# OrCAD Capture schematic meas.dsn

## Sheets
1 UI: size A
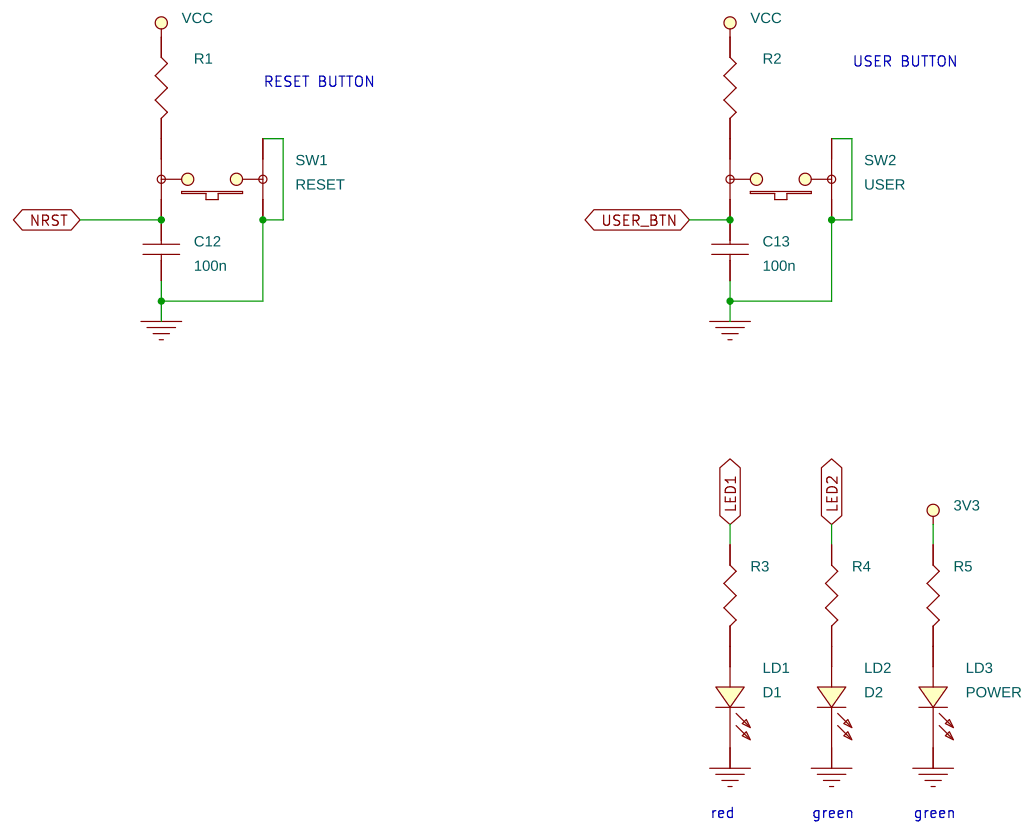
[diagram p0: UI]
2 POWER: size A
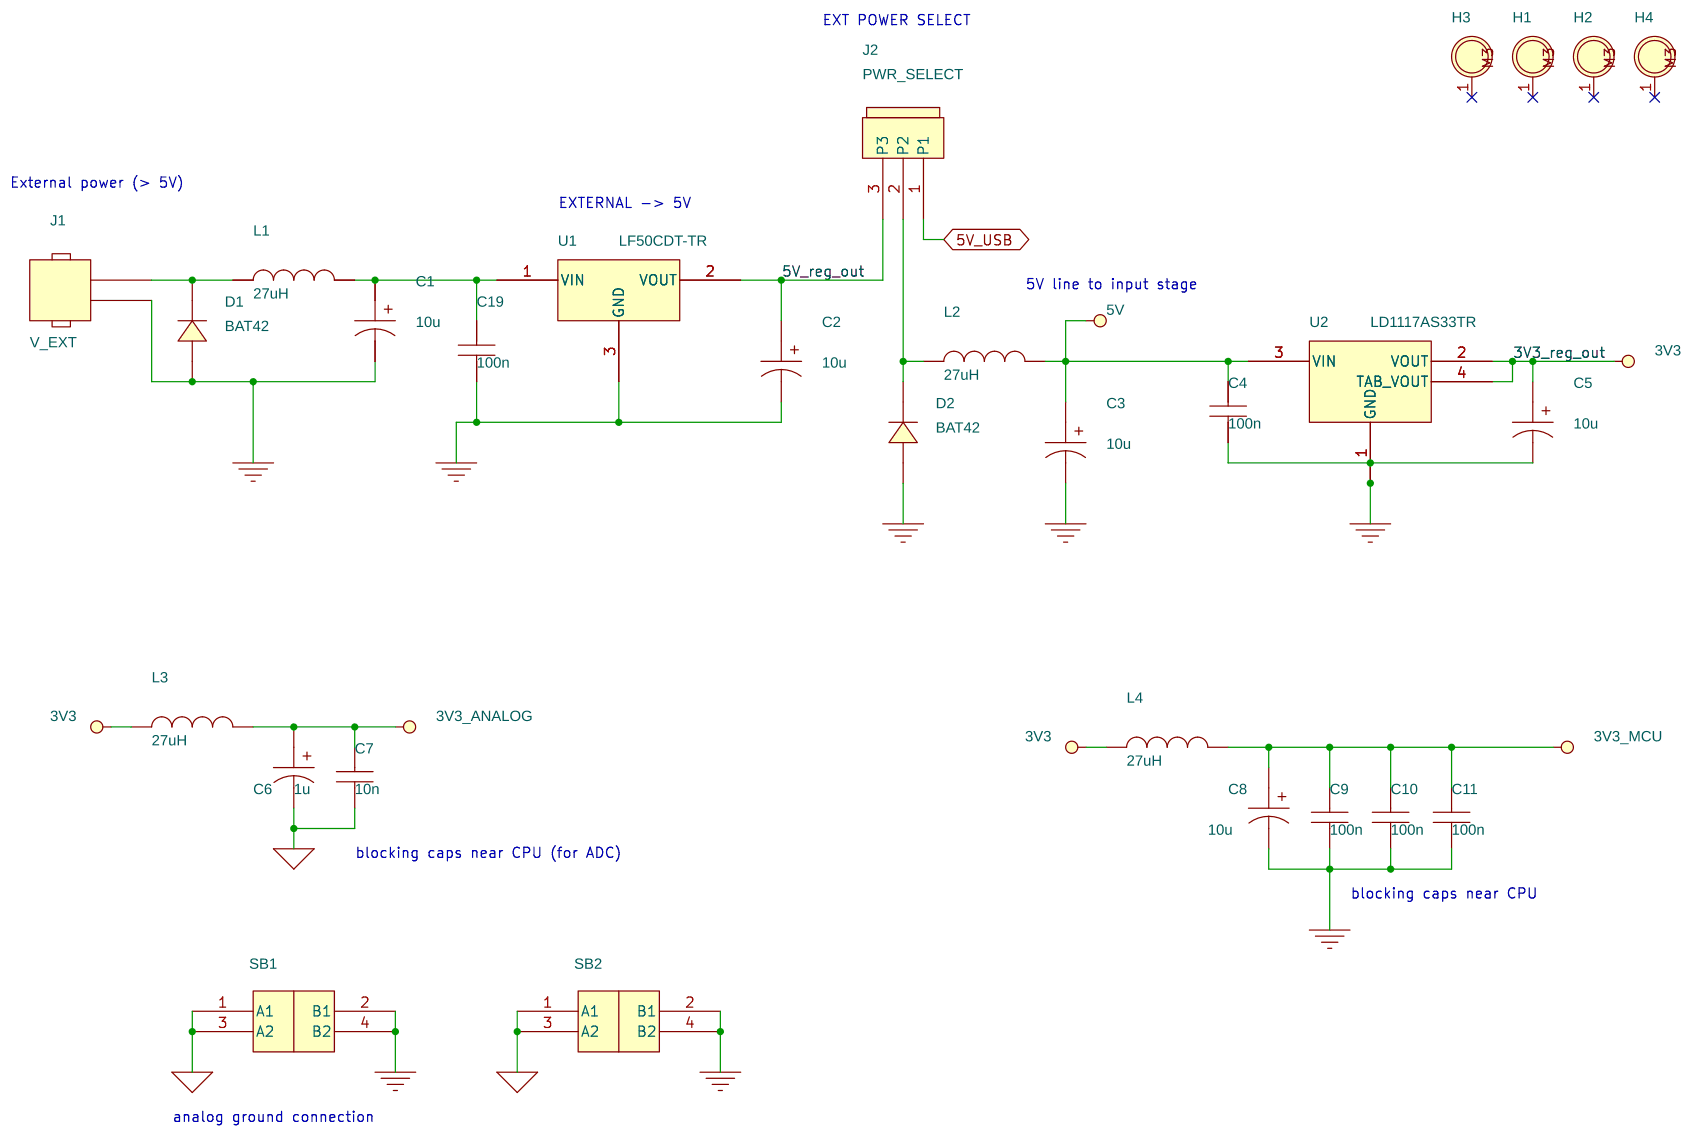
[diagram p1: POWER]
3 INPUT: size A; title: Current measurement and processing; rev: 1
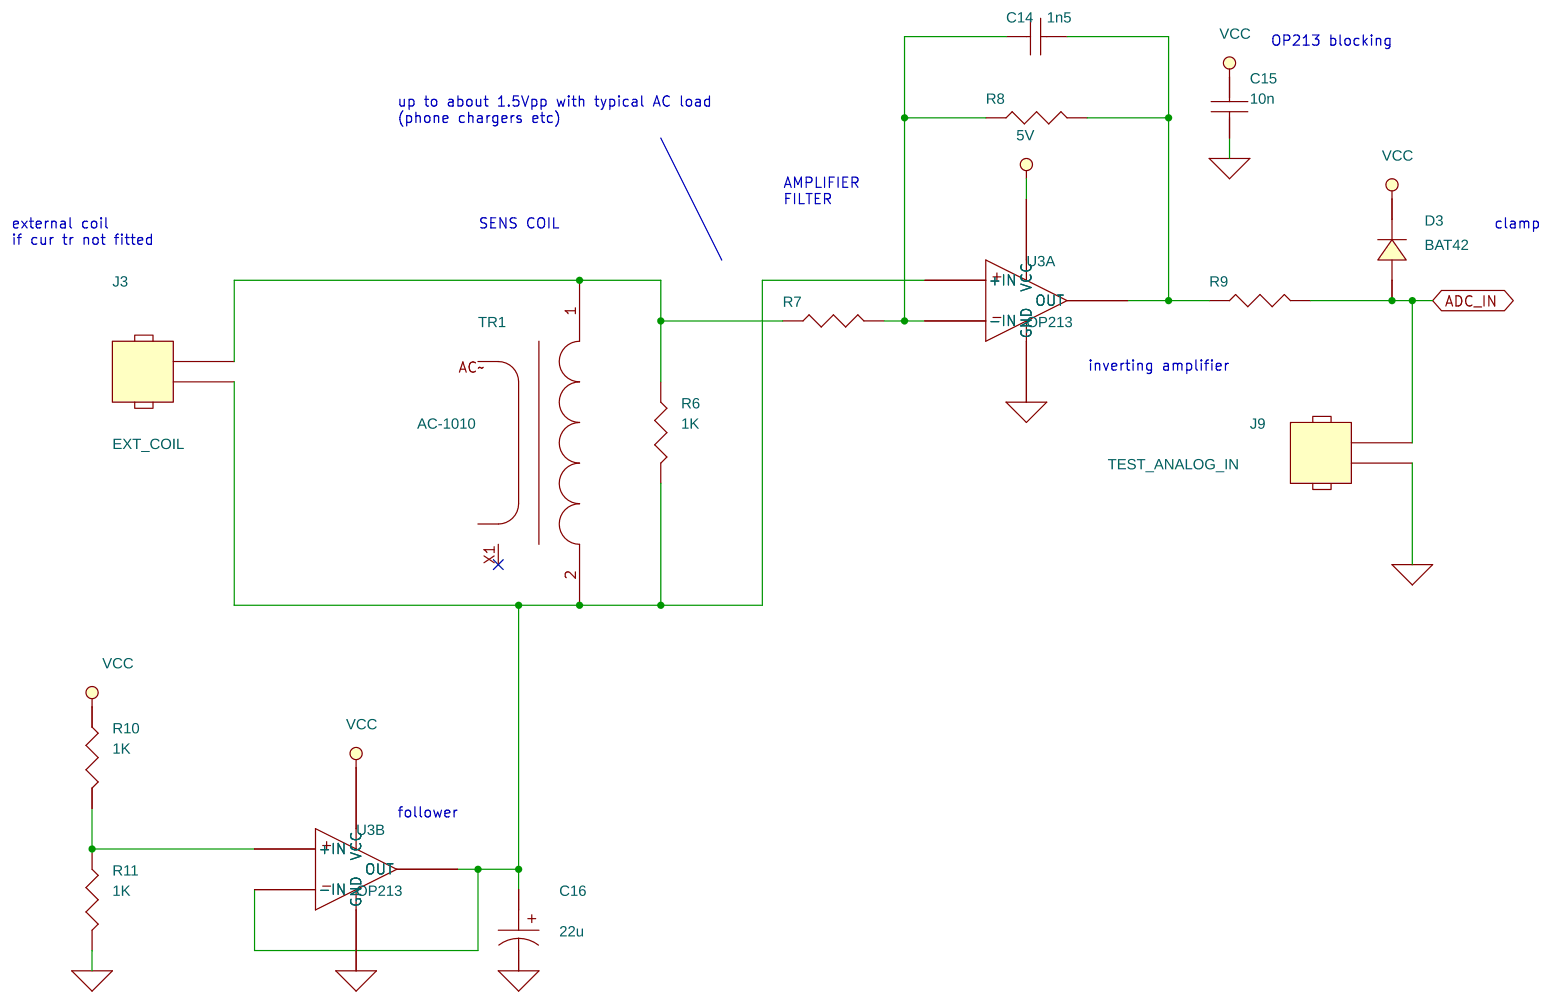
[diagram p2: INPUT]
4 MPU: size B; title: AC current analysys
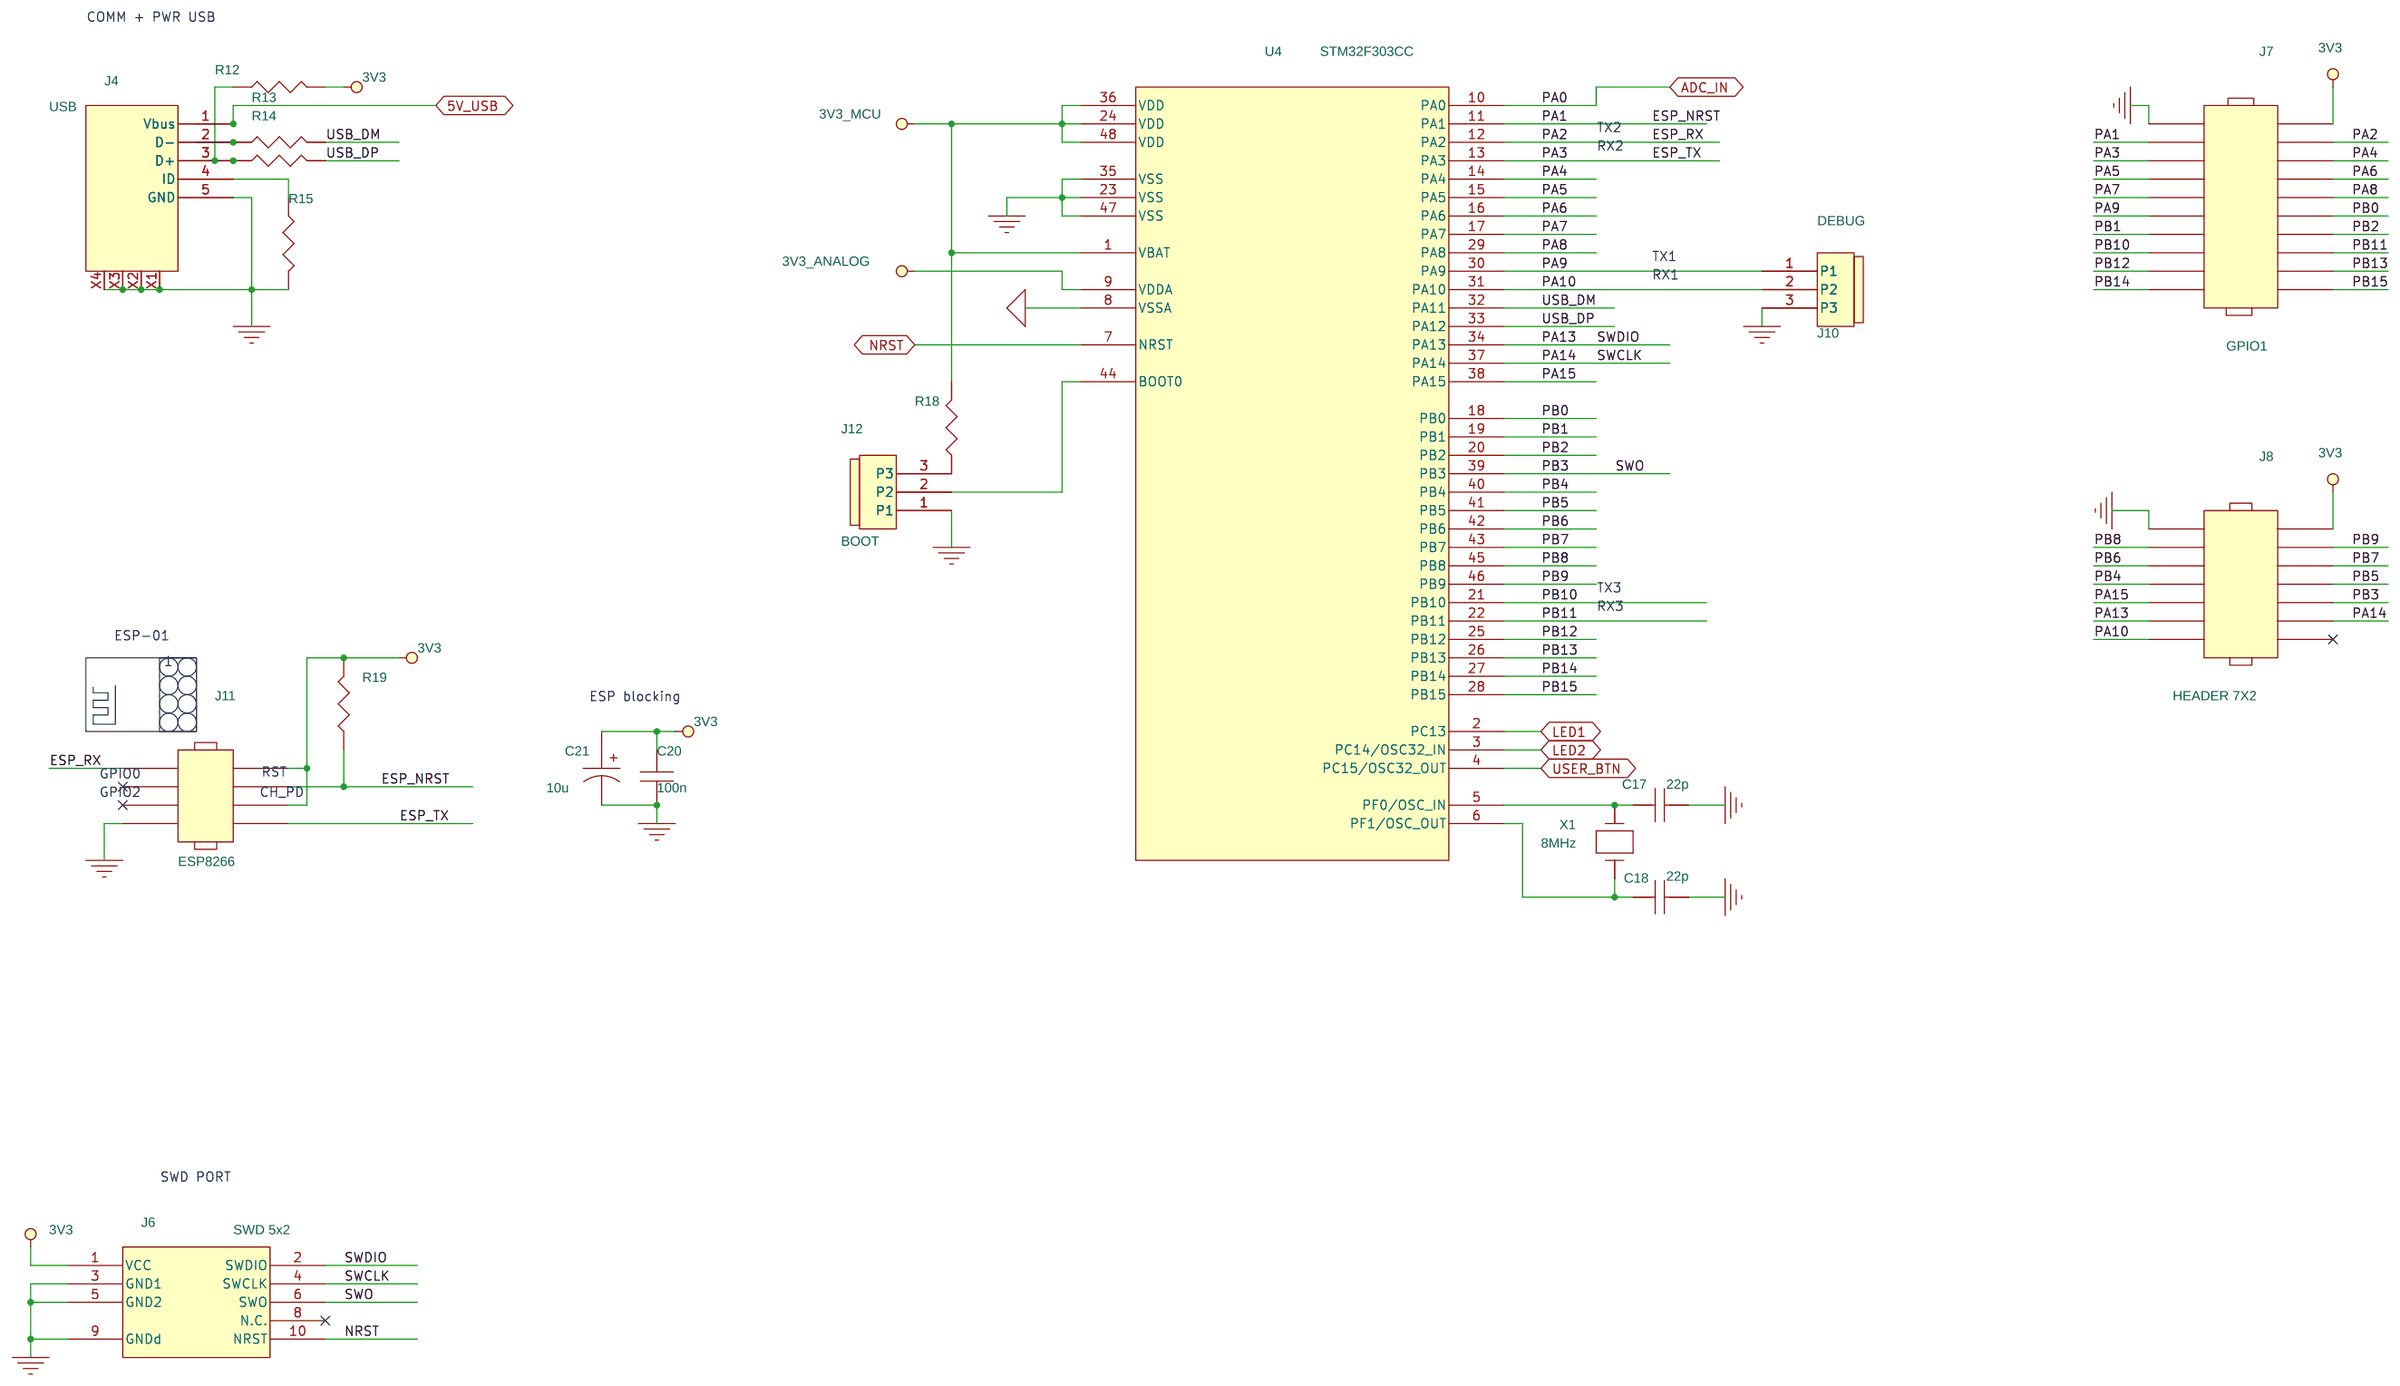
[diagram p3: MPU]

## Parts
sheet INPUT
C14  1n5  [s_0805]
C15  10n  [s_0805]
C16  22u  [s_1206_cap]
D3  BAT42  [s_minimelf]
J3  EXT_COIL  [t_sip2]
J9  TEST_ANALOG_IN  [t_sip2]
R6  1K  [s_0805]
R7  10k  [s_0805]
R8  20k  [s_0805]
R9  470R  [s_0805]
R10  1K  [s_0805]
R11  1K  [s_0805]
TR1  AC-1010  [t_talema_cur_tr]
U3  OP213  [t_dip8]  (sections A,B)
sheet MPU
C17  22p  [s_0805]
C18  22p  [s_0805]
C20  100n  [s_0805]
C21  10u  [s_1206_cap]
J4  USB  [s_usb_mini_b]
J6  SWD 5x2  [t_header_swd]
J7  GPIO1  [t_header10x2]
J8  HEADER 7X2  [t_header7x2]
J10  DEBUG  [t_sip3]
J11  ESP8266  [t_header4x2]
J12  BOOT  [t_sip3]
R12  1k  [s_0805]
R13  22  [s_0805]
R14  22  [s_0805]
R15  100k  [s_0805]
R18  10k  [s_0805]
R19  10k  [s_0805]
U4  STM32F303CC  [s_lqfp48]
X1  8MHz  [t_xtal50]
sheet POWER
C1  10u  [s_1206_cap]
C2  10u  [s_1206_cap]
C3  10u  [s_1206_cap]
C4  100n  [s_0805]
C5  10u  [s_1206_cap]
C6  1u  [s_1206_cap]
C7  10n  [s_0805]
C8  10u  [s_1206_cap]
C9  100n  [s_0805]
C10  100n  [s_0805]
C11  100n  [s_0805]
C19  100n  [s_0805]
D1  BAT42  [s_minimelf]
D2  BAT42  [s_minimelf]
H1  MOUNT HOLE M3  [mount_hole_m3]
H2  MOUNT HOLE M3  [mount_hole_m3]
H3  MOUNT HOLE M3  [mount_hole_m3]
H4  MOUNT HOLE M3  [mount_hole_m3]
J1  V_EXT  [t_power_con]
J2  PWR_SELECT  [t_sip3]
L1  27uH  [s_1210]
L2  27uH  [s_1210]
L3  27uH  [s_1210]
L4  27uH  [s_1210]
SB1  AGND BRIDGE  [t_agnd_bridge]
SB2  AGND BRIDGE  [t_agnd_bridge]
U1  LF50CDT-TR  [s_dpak]
U2  LD1117AS33TR  [s_sot223]
sheet UI
C12  100n  [s_0805]
C13  100n  [s_0805]
LD1  D1  [s_0805_led]
LD2  D2  [s_0805_led]
LD3  POWER  [s_0805_led]
R1  100k  [s_0805]
R2  100k  [s_0805]
R3  150  [s_0805]
R4  150  [s_0805]
R5  150  [s_0805]
SW1  RESET  [t_button_ksm]
SW2  USER  [t_button_ksm]

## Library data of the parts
C4 C7 C9-C15 C17-C20 = CAPACITOR_NON-POL
C1-C3 C5 C6 C8 C16 C21 = CAP_POL
D1-D3 = DIODE
J1 J3 J9 = HEADER_2
R1-R15 R18 R19 = RESISTOR
TR1 = ac-1010
U3 = OP213
J4 = USB_MINI
J6 = SWD_5x2
J7 = HEADER_10X2
J8 = HEADER_7X2
J2 J10 J12 = JUMPER_3
J11 = HEADER_4X2
U4 = stm32f303cct6
X1 = CRYSTAL
H1-H4 = MOUNT_HOLE_M3
L1-L4 = INDUCTOR
SB1 SB2 = AGND_BRIDGE
U1 = LF50CDT-TR
U2 = LD1117AS33TR
LD1-LD3 = LED
SW1 SW2 = SW_PUSHBUTTON-SPST-2

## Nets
3V3: C5.1 C20.1 C21.1 J6.1(VCC) J7.2 J8.2 J11.2 J11.6 L3.1 L4.1 R1.1 R2.1 R5.1 R12.2 R19.2 U2.2(VOUT) U2.4(TAB_VOUT)
3V3_ANALOG: C6.1 C7.1 D3.1(K) L3.2 R10.1 U4.9(VDDA)
3V3_MCU: C8.1 C9.1 C10.1 C11.1 L4.2 R18.2 U4.1(VBAT) U4.24(VDD) U4.36(VDD) U4.48(VDD)
5V: C3.1 C4.1 C15.1 L2.2 U2.3(VIN) U3.8(VCC)
5V_reg_out: C2.1 J2.3(P3) U1.2(VOUT)
5V_USB: J2.1(P1) J4.1(Vbus)
GND: C1.2 C2.2 C3.2 C4.2 C5.2 C8.2 C9.2 C10.2 C11.2 C12.2 C13.2 C17.2 C18.2 C19.2 C20.2 C21.2 D1.2(A) D2.2(A) J1.2 J4.5(GND) J4.X1 J4.X2 J4.X3 J4.X4 J6.3(GND1) J6.5(GND2) J6.9(GNDd) J7.1 J8.1 J10.3(P3) J11.7 J12.1(P1) LD1.1(CATHODE) LD2.1(CATHODE) LD3.1(CATHODE) R15.2 SB1.2(B1) SB1.4(B2) SB2.2(B1) SB2.4(B2) SW1.1 SW1.2 SW2.1 SW2.2 U1.3(GND) U2.1(GND) U4.23(VSS) U4.35(VSS) U4.47(VSS)
GNDA: C6.2 C7.2 C15.2 C16.2 J9.2 R11.2 SB1.1(A1) SB1.3(A2) SB2.1(A1) SB2.3(A2) U3.4(GND) U4.8(VSSA)
ADC_IN: D3.2(A) J9.1 R9.2 U4.10(PA0)
ESP_NRST: J7.3 J11.4 R19.1 U4.11(PA1)
ESP_RX: J7.4 J11.1 U4.12(PA2)
ESP_TX: J7.5 J11.8 U4.13(PA3)
LED1: R3.1 U4.2(PC13)
LED2: R4.1 U4.3(PC14/OSC32_IN)
NRST: C12.1 J6.10(NRST) SW1.4 U4.7(NRST)
PA4: J7.6 U4.14(PA4)
PA5: J7.7 U4.15(PA5)
PA6: J7.8 U4.16(PA6)
PA7: J7.9 U4.17(PA7)
PA8: J7.10 U4.29(PA8)
PA9: J7.11 J10.1(P1) U4.30(PA9)
PA10: J8.13 J10.2(P2) U4.31(PA10)
PA13: J6.2(SWDIO) J8.11 U4.34(PA13)
PA14: J6.4(SWCLK) J8.12 U4.37(PA14)
PA15: J8.9 U4.38(PA15)
PB0: J7.12 U4.18(PB0)
PB1: J7.13 U4.19(PB1)
PB2: J7.14 U4.20(PB2)
PB3: J6.6(SWO) J8.10 U4.39(PB3)
PB4: J8.7 U4.40(PB4)
PB5: J8.8 U4.41(PB5)
PB6: J8.5 U4.42(PB6)
PB7: J8.6 U4.43(PB7)
PB8: J8.3 U4.45(PB8)
PB9: J8.4 U4.46(PB9)
PB10: J7.15 U4.21(PB10)
PB11: J7.16 U4.22(PB11)
PB12: J7.17 U4.25(PB12)
PB13: J7.18 U4.26(PB13)
PB14: J7.19 U4.27(PB14)
PB15: J7.20 U4.28(PB15)
USB_DM: R13.2 U4.32(PA11)
USB_DP: R14.2 U4.33(PA12)
USER_BTN: C13.1 SW2.4 U4.4(PC15/OSC32_OUT)
N31498: J4.3(D+) R12.1 R14.1
N31517: J4.2(D-) R13.1
N33713: C17.1 U4.5(PF0/OSC_IN) X1.1
N33722: C18.1 U4.6(PF1/OSC_OUT) X1.2
N47255: J3.1 R6.1 R7.1 TR1.1
N47331: C14.1 R7.2 R8.1 U3.2(-IN)
N47339: C14.2 R8.2 R9.1 U3.1(OUT)
N47545: C16.1 J3.2 R6.2 TR1.2 U3.3(+IN) U3.6(-IN) U3.7(OUT)
N50175: C1.1 C19.1 L1.2 U1.1(VIN)
N50285: D2.1(K) J2.2(P2) L2.1
N51670: D1.1(K) J1.1 L1.1
N101209: R10.2 R11.1 U3.5(+IN)
N111212: J4.4(ID) R15.1
N117874: R1.2 SW1.3
N117879: R2.2 SW2.3
N127573: J12.2(P2) U4.44(BOOT0)
N127616: J12.3(P3) R18.1
N127774: LD1.2(ANODE) R3.2
N127776: LD2.2(ANODE) R4.2
N127798: LD3.2(ANODE) R5.2

Not connected (* = marked no-connect by the designer): H1 1*; H2 1*; H3 1*; H4 1*; J6 8(N.C.)*; J8 14*; J11 3* 5*; TR1 X1*

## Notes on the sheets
sheet 1
- USER BUTTON
- RESET BUTTON
- red
- green
- green
sheet 2
- EXT POWER SELECT
- External power (> 5V)
- EXTERNAL -> 5V
- 5V line to input stage
- blocking caps near CPU (for ADC)
- blocking caps near CPU
- analog ground connection
sheet 3
- OP213 blocking
- up to about 1.5Vpp with typical AC load
  (phone chargers etc)
- AMPLIFIER
  FILTER
- external coil
  if cur tr not fitted
- SENS COIL
- clamp
- inverting amplifier
- follower
sheet 4
- COMM + PWR USB
- TX2
- RX2
- TX1
- RX1
- TX3
- RX3
- ESP-01
- 1
- ESP blocking
- GPIO0
- RST
- GPIO2
- CH_PD
- SWD PORT
